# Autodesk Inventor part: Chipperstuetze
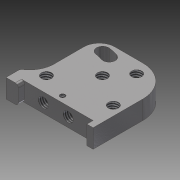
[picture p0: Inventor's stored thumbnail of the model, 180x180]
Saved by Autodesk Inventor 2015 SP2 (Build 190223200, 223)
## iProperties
Created: 2012-07
Part Number: Chipperstuetze
Material: Stahl, galvanisiert
Document SubType Name: Modeling
Designer: rYan
Density: 7.85 g/cm^3
Mass: 18.2784 g
Surface Area: 19.8176 cm^2
Volume: 2.32845 cm^3
Appearance: Galvanisiert
Author: rYan
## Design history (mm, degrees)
sketch "Skizze1"
  geometry: L1 (0, 0)-(28, 0); L2 (28, 24)-(9, 24); L3 (0, 30.043)-(0, -5.007) reference; L4 (-10.4, 0)-(34.4, 0) reference; L5 (0, 2)-(0, 0); L6 (0, 0)-(0, 0); L7 (28, 24)-(28, 0); L8 (4, 19)-(4, 9.483); A1 r 5 centre (9, 19) between (9, 24) and (4, 19); A2 r 1 centre (1, 2) between (0.444, 2.831) and (0, 2); A3 r 8 centre (-4, 9.483) between (0.444, 2.831) and (4, 9.483)
  constraints: 12 end point, 6 point on circle, 5 tangent, 3 centre point, 3 collinear, 2 point on line, 1 horizontal, 1 parallel, 1 perpendicular, 1 vertical
  dimensions: "d26" = 5 radius of A1; "d35" = 28 distance between parallel lines of L7 L3; "d72" = 1 radius of A2; "d98" = 8 radius of A3; "d108" = 2 distance from line of L1 A2.centre; "d109" = 24 distance between parallel lines of L4 L2; "d130" = 4 distance between parallel lines of L3 L8
extrude "Extrusion1" new body sketch "Skizze1" stored distance "d3" = 6; taper "d4" = 0 deg
sketch "Skizze2"
  geometry: L1 (0, 28.8)-(0, -4.8) reference; L2 (-5.6, 0)-(33.6, 0) reference; 2 further points
  dimensions: "d38" = 15 distance from line of point (15, 14) L1; "d125" = 14 distance from line of L2 point (15, 14)
hole "Chipachse" sketch "Skizze2" at (15, 14) diameter "d6" = 3.242; stored, may be unused: countersink angle "d10" = 90 deg, drill point angle "d12" = 118 deg; dims "d7" = 8, "d8" = 4, "d9" = 2, "d11" = 8
sketch "Skizze3"
  geometry: L1 (-5.6, 0)-(33.6, 0) reference; L2 (0, 28.8)-(0, -4.8) reference; 1 further point
  dimensions: "d106" = 6 distance from line of point (6, 5) L2; "d107" = 5 distance from line of point (6, 5) L1
hole "Aufbauachse" sketch "Skizze3" at (6, 5) diameter "d18" = 3.242; stored, may be unused: countersink angle "d22" = 90 deg, drill point angle "d24" = 118 deg; dims "d19" = 8, "d20" = 4, "d21" = 2, "d23" = 8
sketch "Skizze7"
  geometry: L1 (14, 6)-(14, 0); L2 (28, 0)-(0, 0) reference; L3 (0, 6)-(28, 6) reference; L4 (0, 0)-(0, 6) reference; L5 (28, 6)-(28, 0) reference; L6 (0, 0)-(0, 6) reference; L7 (0, 3)-(28, 3); 2 further points
  constraints: 4 end point, 4 midpoint, 2 point on line
  dimensions: "d143" = 8 distance of point (18, 3) point (10, 3); "d144" = 4 distance from line of point (10, 3) L1
hole "Montage" sketch "Skizze7" at (10, 3), (18, 3) diameter "d77" = 3.242; stored, may be unused: countersink angle "d81" = 90 deg, drill point angle "d83" = 118 deg; dims "d78" = 8, "d79" = 4, "d80" = 2, "d82" = 5
workplane "Arbeitsebene1"
  workpoint "Arbeitspunkt1"
sketch "Skizze15"
  geometry: L1 (6, 5)-(10.944, 20.217); L2 (6, 5)-(8.227, 20.844); L3 (0, 37.981)-(0, -27.981) reference; L4 (6, 5)-(6, 28.558); C1 r 1.621 at (6, 5) reference; A1 r 16 centre (6, 5) between (10.944, 20.217) and (8.227, 20.844); A2 r 17.95 centre (6, 5) between (11.547, 22.071) and (8.498, 22.775); A3 r 14.05 centre (6, 5) between (10.342, 18.362) and (7.955, 18.913); A4 r 1.95 centre (10.944, 20.217) between (10.342, 18.362) and (11.547, 22.071); A5 r 1.95 centre (8.227, 20.844) between (8.498, 22.775) and (7.955, 18.913); 1 further point
  constraints: 10 point on circle, 6 end point, 5 centre point, 4 tangent, 2 coincident, 1 vertical, 1 vertical alignment, 2 other
  dimensions: "d169" = 16 radius of A1; "d170" = 10 deg angle of L1 L2; "d171" = 3.9 diameter of A4; "d175" = 8 deg angle of L2 L4
extrude "Dribblerbereich" cut sketch "Skizze15" stored distance "d173" = 10; taper "d174" = 0 deg
sketch "Skizze16"
  geometry: L1 (28, 0)-(28, -6) reference; L2 (0, 0)-(28, 0) reference; L3 (0, -6)-(0, 0) reference; L4 (28, -6)-(0, -6) reference; L5 (28, -6)-(26, -6); L6 (26, -6)-(26, 0); L7 (26, 0)-(28, 0); L8 (28, 0)-(28, -6); L9 (0, -6)-(4, -6); L10 (4, -6)-(4, 0); L11 (4, 0)-(0, 0); L12 (0, 0)-(0, -6); C1 r 1.621 at (10, -3) reference; C2 r 1.621 at (18, -3) reference; 1 further point
  constraints: 16 end point, 4 parallel, 2 horizontal, 2 perpendicular, 2 point on line
  dimensions: "d176" = 2 distance between parallel lines of L1 L6; "d177" = 4 distance between parallel lines of L3 L10
extrude "Extrusion4" join sketch "Skizze16" distance "d178" = 2; taper "d179" = 0 deg
fillet "Rundung2" dims "d181" = 1
sketch "Skizze17"
  geometry: C1 r 1.621 at (15, 14) reference; 2 further points
  dimensions: "d182" = 12 vertical distance of point (14.2, 2) C1.centre; "d192" = 0.8 horizontal distance of point (14.2, 2) C1.centre
hole "Bohrung12" sketch "Skizze17" at (14.2, 2) diameter "d184" = 1.567; stored, may be unused: countersink angle "d188" = 90 deg, drill point angle "d190" = 118 deg; dims "d185" = 4, "d186" = 4, "d187" = 2, "d189" = 6.3
sketch "Skizze18"
  geometry: L1 (0, 29.2)-(0, -7.2) reference; L2 (-5.6, 0)-(33.6, 0) reference; 2 further points
  dimensions: "d193" = 20 distance from line of point (20, 20) L2; "d194" = 20 distance from line of point (20, 20) L1
hole "Bohrung13" sketch "Skizze18" at (20, 20) diameter "d195" = 3.242; stored, may be unused: countersink angle "d199" = 90 deg, drill point angle "d201" = 118 deg; dims "d196" = 8, "d197" = 4, "d198" = 2, "d200" = 11.8
sketch "Skizze19"
  geometry: L1 (0, 29.2)-(0, -7.2) reference; L2 (-5.6, 0)-(33.6, 0) reference; 2 further points
  dimensions: "d202" = 25 distance from line of point (25, 7.5) L1; "d203" = 7.5 distance from line of point (25, 7.5) L2
hole "Bohrung14" sketch "Skizze19" at (25, 7.5) diameter "d204" = 3.242; stored, may be unused: countersink angle "d208" = 90 deg, drill point angle "d210" = 118 deg; dims "d205" = 8, "d206" = 4, "d207" = 2, "d209" = 11.8
fillet "Rundung3" dims "d211" = 10
node "Volumenkörper1"
node "Projizierte Kontur2"
workaxis "Arbeitsachse1"
node "Projizierte Kontur6"
other parameters: "d32" = 16
